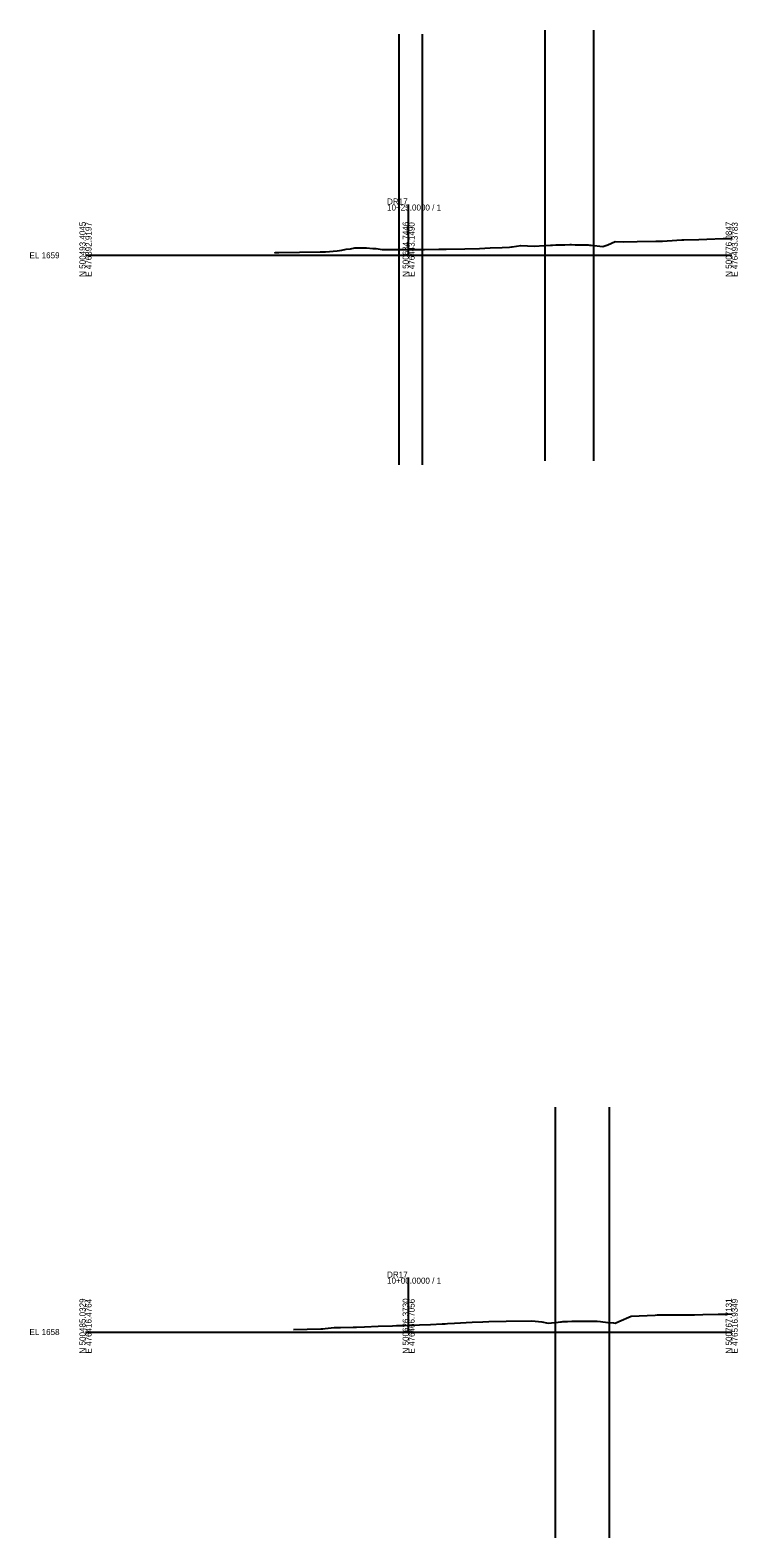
# Model space of a CAD drawing. Extents: x -26 to 303, y -96 to 3030.
# Drawn here: x -26 to 303, y -96 to 605 of the extents above; entities that cross this region are included whole.
import ezdxf

# ---------------------------------------------------------------- set-up
doc = ezdxf.new("R2010")
doc.units = 0
for name, color, linetype in [('Exist Cross Section Cell', 7, 'Continuous'), ('Exist XS Center Line Elevation Label', 7, 'Continuous'), ('Exist XS Ground Line', 7, 'Continuous'), ('Scratch_Level_2', 7, 'Continuous')]:
    doc.layers.add(name, color=color, linetype=linetype)

msp = doc.modelspace()

# ---------------------------------------------------------------- linework, layer by layer
at = {"layer": 'Exist Cross Section Cell'}
for p, q in [((150, 500), (150, 523.6)), ((0, 500), (150, 500)), ((150, 500), (300, 500)), ((150, 0), (150, 25.27)), ((0, 0), (150, 0)), ((150, 0), (300, 0))]:
    msp.add_line(p, q, dxfattribs=at)
at = {"layer": 'Exist XS Ground Line'}
for points in [[(87.73, 501.22), (88.19, 501.29), (89.7, 501.37), (108.93, 501.57), (110.24, 501.63), (111.4, 501.67), (116.82, 502.12), (118.96, 502.44), (120.94, 502.89), (122.99, 503.02), (125.06, 503.41), (127.36, 503.46), (130.42, 503.46), (133.4, 503.23), (134.97, 503.1), (137.66, 502.7), (139.51, 502.66), (142.64, 502.63), (145.54, 502.66), (150, 502.7), (153.53, 502.73), (157.45, 502.76), (163.97, 502.84), (166.31, 502.9), (167.48, 502.92), (176.13, 502.99), (182.91, 503.22), (187.93, 503.44), (193.42, 503.62), (196.83, 503.79), (197.74, 503.87), (198.15, 503.92), (202.09, 504.55), (208.23, 504.28), (213.14, 504.54), (215.91, 504.72), (216.34, 504.74), (216.85, 504.76), (218.36, 504.84), (219.45, 504.9), (221.51, 504.92), (222.08, 504.93), (222.5, 504.94), (224.79, 504.97), (225.56, 504.96), (227.37, 504.94), (228.96, 504.92), (230.02, 504.91), (231.7, 504.86), (232.68, 504.82), (233.41, 504.8), (233.99, 504.78), (234.75, 504.7), (240.24, 504.04), (242.44, 504.82), (245.95, 506.42), (249.81, 506.2), (256.11, 506.39), (264.79, 506.53), (267.88, 506.63), (274.5, 507.06), (276.9, 507.19), (277.75, 507.23), (284.73, 507.42), (288.37, 507.46), (296.01, 507.74), (298.98, 507.85), (300, 507.87)], [(96.55, 1.19), (109.31, 1.51), (110.18, 1.55), (111.31, 1.6), (115.37, 2.06), (116.51, 2.08), (118.33, 2.16), (124.24, 2.18), (124.6, 2.21), (125.45, 2.27), (125.83, 2.29), (129.56, 2.42), (135.93, 2.66), (142.51, 2.88), (144.38, 2.95), (148.15, 3.08), (150, 3.14), (160.23, 3.5), (165.6, 3.76), (166.93, 3.84), (168.11, 3.89), (171.27, 4.07), (179.43, 4.5), (184.42, 4.75), (187.24, 4.86), (195.23, 5.06), (207.24, 5.17), (211.8, 4.7), (214.74, 4.12), (219.4, 4.62), (220.56, 4.76), (220.91, 4.79), (221.58, 4.83), (223.03, 4.91), (223.77, 4.93), (225.83, 5.01), (228.31, 5.06), (229.75, 5.1), (230.95, 5.09), (233.59, 5.11), (235.48, 5.06), (236.26, 5.04), (237.54, 5), (239.01, 4.94), (242.43, 4.49), (245.16, 4.19), (245.84, 4.13), (247.52, 4.84), (253.32, 7.36), (264.43, 7.9), (265.41, 7.95), (272.84, 7.96), (276.02, 7.99), (282.71, 8.05), (286.64, 8.07), (293.76, 8.22), (296.34, 8.28), (297.25, 8.31), (298, 8.34), (300, 8.42)]]:
    msp.add_lwpolyline(points, dxfattribs=at)
at = {"layer": 'Scratch_Level_2'}
for p, q in [((145.5, 602.66), (145.5, 402.66)), ((156.31, 602.75), (156.31, 402.75)), ((213.28, 604.55), (213.28, 404.55)), ((235.89, 604.57), (235.89, 404.57)), ((218.1, 104.48), (218.1, -95.52)), ((243.09, 104.42), (243.09, -95.58))]:
    msp.add_line(p, q, dxfattribs=at)

# ---------------------------------------------------------------- texts
at = {"layer": 'Exist Cross Section Cell'}
for s, p in [('DR17', (140, 523.6)), ('10+25.0000 / 1', (140, 520.8)), ('EL 1659', (-26, 498.6)), ('DR17', (140, 25.27)), ('10+00.0000 / 1', (140, 22.47)), ('EL 1658', (-26, -1.4))]:
    msp.add_text(s, height=2.8, dxfattribs=at).set_placement(p)
for s, p in [('N 500493.4045', (0, 490)), ('E 476392.9197', (2.8, 490)), ('N 500634.7446', (150, 490)), ('E 476443.1490', (152.8, 490)), ('N 500776.0847', (300, 490)), ('E 476493.3783', (302.8, 490)), ('N 500485.0329', (0, -10)), ('E 476416.4764', (2.8, -10)), ('N 500626.3730', (150, -10)), ('E 476466.7056', (152.8, -10)), ('N 500767.7131', (300, -10)), ('E 476516.9349', (302.8, -10))]:
    msp.add_text(s, height=2.8, rotation=90, dxfattribs=at).set_placement(p)
at = {"layer": 'Exist XS Center Line Elevation Label'}
for s, p in [('1661.70', (148.45, 499.95)), ('1661.14', (148.6, 0.39))]:
    msp.add_text(s, height=0.75, dxfattribs=at).set_placement(p)

doc.saveas('drawing.dxf')
